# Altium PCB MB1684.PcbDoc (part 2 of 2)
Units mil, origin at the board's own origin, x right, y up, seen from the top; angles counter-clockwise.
Board outline 3937.01 x 905.51 mil, 2 copper layers (Top Layer, Bottom Layer), stack 61.811 mil thick; 71 components, 77 nets, 327 pads, 286 vias.
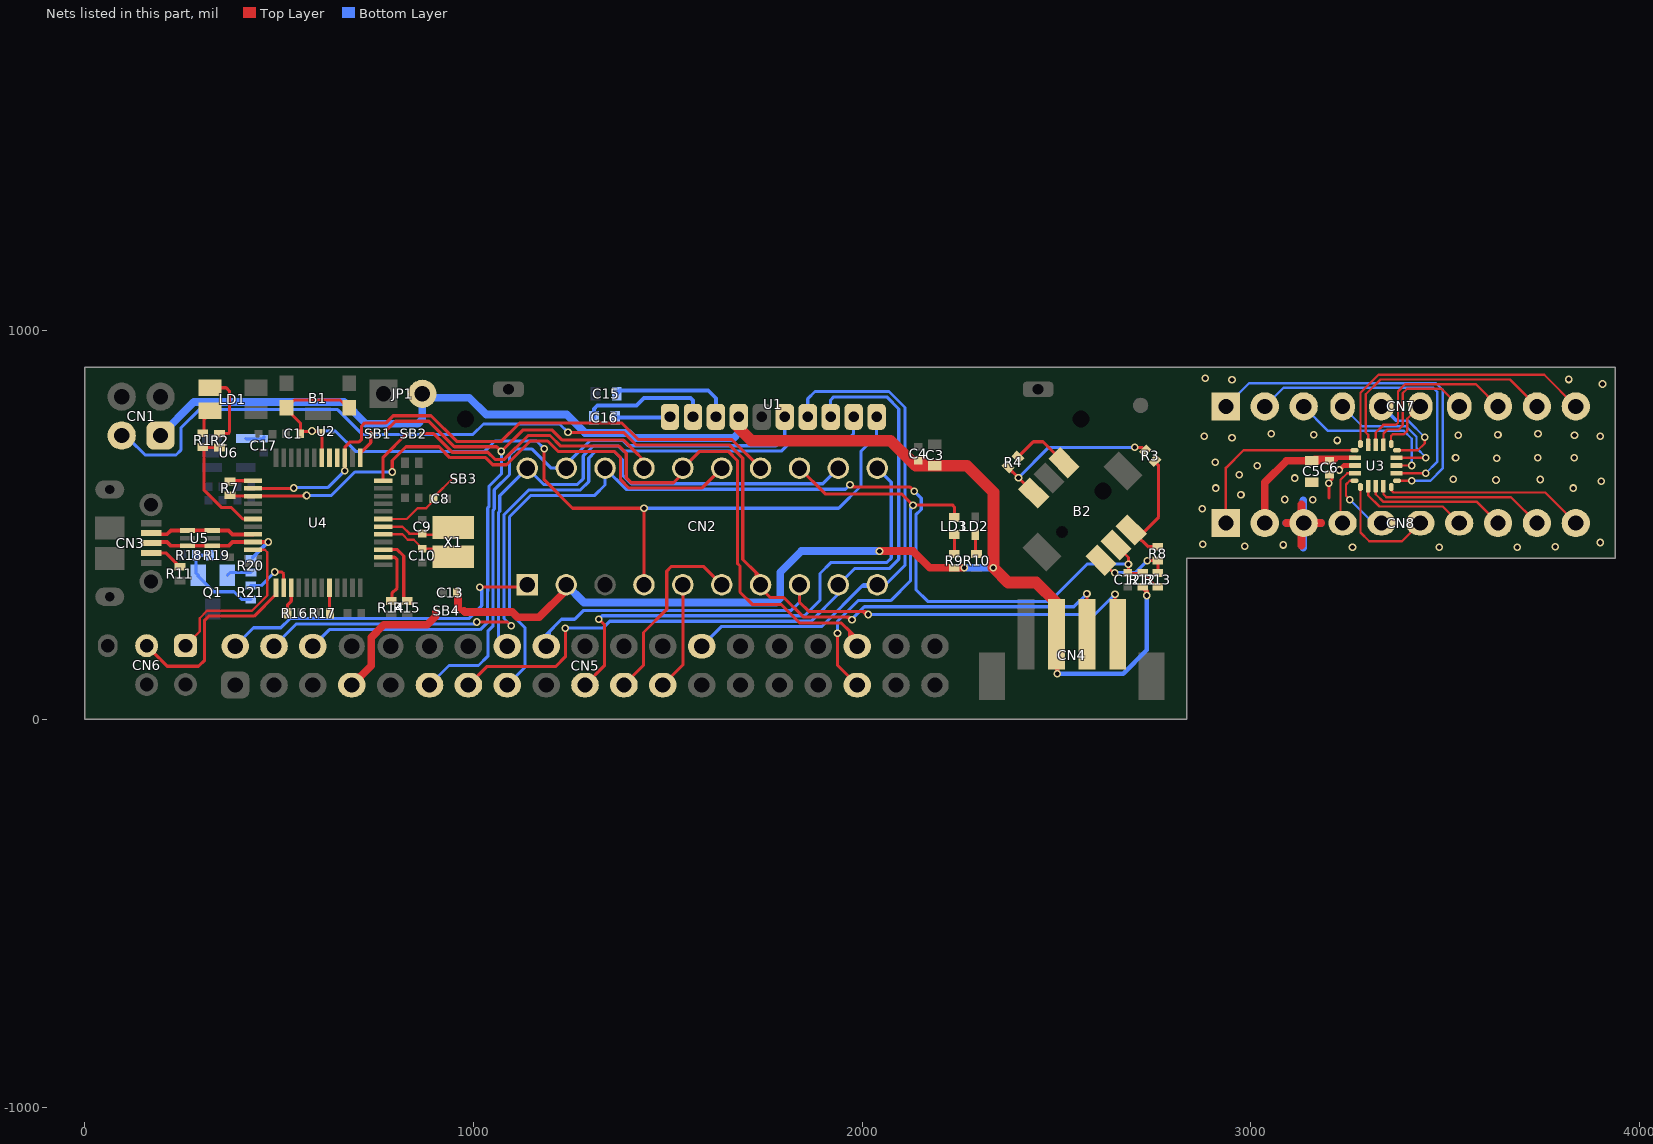
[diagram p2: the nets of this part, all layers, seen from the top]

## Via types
v1: diameter 19.68, hole 11.81, Top Layer to Bottom Layer, tented both sides, 286 vias

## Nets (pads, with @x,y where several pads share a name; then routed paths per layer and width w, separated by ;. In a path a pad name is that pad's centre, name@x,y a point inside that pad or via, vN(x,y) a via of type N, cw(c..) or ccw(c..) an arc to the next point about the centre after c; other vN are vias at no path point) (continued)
NetB2_1: B2.1 R8.1 R13.2 | length 212.5
  Top Layer w8: B2.1@2614.26,408.9 2646.81,376.34 v1(2649.48,376.34) ; v1(2733.85,407.77) 2760.72,407.77 R8.1@2760.83,407.88 R13.2@2760.83,375.77
  Bottom Layer w8: v1@2644.85,376.77 2702.85,376.77 v1(2733.85,407.77) 2736.27,407.77 v1@2736.53,407.52
NetB2_3: B2.3 R3.1 R8.2 | length 306.9
  Top Layer w8: B2.3@2700.54,478.51 B2.3@2705.63,473.42 ; R3.1@2753.37,665.14 2753.37,661.18 2762.85,651.7 2762.85,519.47 2716.79,473.42 B2.3@2705.63,473.42 ; R3.1@2757.98,665.14 R3.1@2757.98,671.28 ; R8.2@2760.83,443.31 2735.74,443.31 B2.3@2705.63,473.42
NetB2_4: B2.4 R3.2 R4.1 | length 456.1
  Top Layer w8: R4.1@2375.03,648.12 v1(2402.4,620.75) B2.4@2441.65,581.5 ; v1(2701.4,698.93) 2706.17,698.93 2719.59,698.93 R3.2@2728.32,690.2
  Bottom Layer w8: v1(2402.4,620.75) 2480.58,698.93 v1(2701.4,698.93)
NetB2_6: B2.6 R4.2 | length 157.7
  Top Layer w8: R4.2@2400.81,673.9 2440.51,713.6 2465.45,713.6 B2.6@2519.6,659.45
NetC15_2: C15.2 U1.8 | length 314.1
  Bottom Layer w10: C15.2@1369.19,836.61 1377.51,844.93 1604.4,844.93 1624.02,825.32 U1.8@1624.02,777.56
NetC16_1: C16.1 U1.10 | length 141.5
  Bottom Layer w10: C16.1@1365.26,775.59 1503.94,775.59 U1.10@1505.91,777.56
NetC16_2: C16.2 U1.9 | length 333.6
  Bottom Layer w10: C16.2@1310.14,775.59 1310.14,798.1 1318.96,806.93 1420.12,806.93 1438.97,825.78 1559.11,825.78 1564.96,819.93 U1.9@1564.96,777.56
NetC17_2: C17.2 U6.4 | length 48.9
  Bottom Layer w8: U6.4@414.64,722 415.66,720.98 C17.2@461.13,720.98 ; C17.2@461.13,726.03 C17.2@463.13,726.03
NetCN3_4: CN3.4 R11.2 | length 88.6
  Top Layer w8.27: CN3.4@171.26,427.17 210.3,427.17 R11.2@245.35,392.11
NetCN5_7: CN5.7 SB4.2 | length 341.2
  Top Layer w20: CN5.7@687.4,87.8 737.4,137.8 737.4,209.89 770.06,242.55 881.18,242.55 903.22,264.58 903.22,274.55
NetLD1_2: LD1.2 R1.2 | length 67.5
  Top Layer w7.87: R1.2@307.09,735.23 307.09,770.46 LD1.2@329.92,793.3
NetLD1_3: LD1.3 R2.2 | length 179.7
  Top Layer w7.87: LD1.3@329.92,852.35 364.28,852.35 373.15,843.49 373.15,738.06 369.34,734.25 R2.2@347.4,734.25
NetLD2_1: LD2.1 R10.1 | length 49.5
  Top Layer w8: R10.1@2291.54,424.99 LD2.1@2291.54,474.45
NetLD3_1: LD3.1 R9.1 | length 55.4
  Top Layer w8: R9.1@2237.4,424.99 LD3.1@2237.4,480.35
NetQ1_1: Q1.1 R18.2 R19.1 R21.1 | length 248.4
  Bottom Layer w8: R19.1@319.17,421.71 R18.2@287.1,421.71 287.1,375.32 Q1.1@292.52,369.9 292.52,367.2 332.13,327.6 384.33,327.6 403.81,308.11 R21.1@427.63,308.11
NetQ1_2: Q1.2 R20.2 | length 63.8
  Bottom Layer w8: Q1.2@367.32,369.9 374.64,377.22 R20.2@428.13,377.22
NetR14_2: R14.2 U4.2 | length 150.1
  Top Layer w8: U4.2@768.03,416.34 797.77,416.34 804.22,409.89 804.22,336.96 790.67,323.42 R14.2@790.67,304.26
NetR15_2: R15.2 U4.3 | length 178.9
  Top Layer w8: U4.3@768.03,436.02 804.7,436.02 821.13,419.6 821.13,313.18 R15.2@830.04,304.26
NetR16_1: R16.1 U4.39 | length 76
  Top Layer w8: R16.1@522.59,272.55 522.59,294.2 531.81,303.42 U4.39@531.81,337.6 U4.39@531.81,344.75
NetR17_2: R17.2 U4.44 | length 72.4
  Top Layer w8: R17.2@629.78,272.55 630.24,273 U4.44@630.24,337.6 U4.44@630.24,344.75
NRST: B1.1 B1.3 C1.2 CN2.7 U1.1 U2.1 U4.18 | length 2353.4
  Top Layer w7.87: C1.2@559.13,738.6 C1.2@557.31,740.41 ; U2.1@605.74,742.6 U2.1@603.55,740.41 ; U2.1@609.82,740.41 U2.1@603.55,740.41 ; U4.18@610.55,679.39 U2.1@610.55,740.41 ; B1.3@681.1,799.47 B1.3@681.1,801.17 677.12,801.17 657.2,821.1 539.61,821.1 B1.1@519.68,801.17 526.13,794.73 526.13,790.6 555.13,761.6 555.13,742.6 C1.2@557.31,740.41 ; v1(1182.13,695.65) 1182.13,615.6 1255.18,542.54 v1(1439.1,542.54) 1439.1,345.78 CN2.7@1438.98,345.65 ; C1.2@557.31,740.41 U2.1@603.55,740.41
  Bottom Layer w7.87: v1(585.13,741.25) 645.27,741.25 697.73,688.78 1029.52,688.78 1055.99,715.25 1162.53,715.25 v1(1182.13,695.65) ; v1(1439.1,542.54) 1939.82,542.54 1997.1,599.82 1997.1,689.39 2037.4,729.69 U1.1@2037.4,777.56
OSC_IN: C10.2 U4.5 X1.1 | length 208.1
  Top Layer w6: U4.5@768.03,475.39 817.69,475.39 831.69,461.39 846.22,461.39 846.38,461.24 846.8,461.24 C10.2@869.58,438.46 ; C10.2@869.5,438.46 C10.2@869.58,438.46 ; C10.2@873.44,438.3 869.74,438.3 C10.2@869.58,438.46 ; X1.1@948.24,417.73 927.51,438.46 C10.2@869.58,438.46
OSC_OUT: C9.2 U4.6 X1.2 | length 199.2
  Top Layer w6: U4.6@768.03,495.08 817.8,495.08 835.61,477.27 C9.2@872.57,477.27 ; C9.2@868.63,474.07 929.78,474.07 X1.2@948.24,492.53
PA0: CN2.9 CN5.23 | length 279.2
  Top Layer w8: CN5.23@1487.4,87.8 1538.98,139.37 CN2.9@1538.98,345.65
PA1: CN2.11 CN5.21 | length 504.7
  Top Layer w8: CN5.21@1387.4,87.8 1437.98,138.37 1437.98,222.99 1497.57,282.58 1497.57,380.85 1509.69,392.97 1591.66,392.97 CN2.11@1638.98,345.65
PA2: CN1.2 CN2.13 CN4.2 | length 3166.9
  Top Layer w8: v1(1243.57,737.6) 1386.53,737.6 1418.63,705.49 1658.68,705.49 1693.13,671.05 1693.13,410.72 1727.65,376.2 ; CN2.13@1727.65,337.33 1727.65,376.2 ; 1727.65,376.39 1727.65,376.2 ; 1960.96,262.85 v1@1968.82,255 ; v1(1974.13,255.25) 1966.27,263.1 1848.32,263.1 1798.34,313.09 1763.92,313.09 1738.98,338.03 CN2.13@1738.98,345.65 1738.98,364.87 1727.65,376.2 ; v1(2578.4,322.93) 2578.4,218.17 CN4.2@2578.74,218.5
  Bottom Layer w8: CN1.2@115.35,729.53 115.35,719.92 155.96,679.31 235.42,679.31 248,691.89 248,749 295,796 651.1,796 714.64,732.46 999.43,732.46 1026.26,759.29 1221.87,759.29 v1(1243.57,737.6) ; v1@1975.13,258.25 2005.98,289.1 2544.58,289.1 v1(2578.4,322.93)
PA3: CN2.15 CN4.1 CN5.18 | length 1814.1
  Top Layer w8: CN2.15@1838.98,345.65 1838.98,301.02 1862.9,277.1 2008.13,277.1 v1(2015.98,269.26) ; 2002.96,276 v1@2010.82,268.15 ; CN4.1@2647.03,208.05 CN4.1@2647.4,207.68 ; v1(2650.59,321.57) 2650.59,225.39 CN4.1@2657.48,218.5
  Bottom Layer w8: CN5.18@1196.43,194.47 CN5.18@1196.43,196.83 ; 1196.43,224.04 CN5.18@1196.43,196.83 ; CN5.18@1198.34,198.73 CN5.18@1196.43,196.83 ; CN2.15@1838.98,345.65 1838.98,301.02 1817.88,279.93 1283.74,279.93 1260.79,256.98 1227.01,256.98 1187.4,217.36 CN5.18@1187.4,187.8 CN5.18@1196.43,196.83 ; v1(2015.98,269.26) 2598.28,269.26 v1(2650.59,321.57)
PA4: CN2.17 CN5.13 U1.3 | length 1919
  Top Layer w8: CN5.13@987.4,87.8 1034.58,134.98 1211.48,134.98 1236.84,160.34 v1(1236.84,233.98)
  Bottom Layer w8: v1(1236.84,233.98) 1332.89,233.98 1350.84,251.93 1868.98,251.93 1938.98,321.92 CN2.17@1938.98,345.65 1980.58,387.26 2070.07,387.26 2094.4,411.59 2094.4,797.93 2063.52,828.81 1927.29,828.81 1919.29,820.81 U1.3@1919.29,777.56
PA5: CN2.19 CN5.26 U1.4 | length 1372.1
  Bottom Layer w8: CN5.26@1587.4,187.8 1637.53,237.93 1895.64,237.93 2003.37,345.65 CN2.19@2038.98,345.65 2060.25,345.65 2110.4,395.81 2110.4,801.73 2069.32,842.81 1879.12,842.81 1860.24,823.93 U1.4@1860.24,777.56 ; 1999.84,340.98 CN2.19@2035.45,340.98
PA6: CN2.2 CN5.16 U1.2 | length 1502.2
  Bottom Layer w8: CN5.16@1087.4,187.8 1078.16,187.8 1065.11,200.85 1065.11,531.77 1067.95,534.61 1067.95,574.62 CN2.2@1138.98,645.65 1181.04,603.59 1267.8,603.59 1282.98,618.76 1282.98,677.26 1307.98,702.26 1373.98,702.26 1386.98,689.26 1792.4,689.26 1823.14,720 1963.77,720 1978.35,734.57 U1.2@1978.35,777.56
PA7: CN2.4 CN5.11 U1.5 | length 1560.3
  Bottom Layer w8: CN5.11@887.4,87.8 937.53,137.93 1013.53,137.93 1037.4,161.8 1037.4,226.45 1051.1,240.15 1051.1,323.61 ; 1051.11,323.62 1051.11,537.56 1053.95,540.41 1053.95,589.77 1093.13,628.95 1093.13,678.8 1108.87,694.55 1151.25,694.55 1200.14,645.65 CN2.4@1238.98,645.65 1244.53,645.65 1244.53,660.65 1300.13,716.26 1385.77,716.26 1398.77,703.26 1779.03,703.26 1801.18,725.41 U1.5@1801.18,777.56
PA8: B2.2 C12.2 CN2.6 CN5.15 R12.2 R13.1 | length 2669.2
  Top Layer w6: C12.2@2685.44,375.77 R12.2@2721.66,375.77 2723.96,375.77 2759.39,340.34 R13.1@2760.83,340.34
  Top Layer w8: v1(1968.86,602.8) 1975.02,596.64 2123.56,596.64 v1(2134.4,585.8) ; v1@1973.32,603.5 1979.48,597.34 ; B2.2@2653.23,447.87 2685.13,415.98 v1(2685.13,398.6) 2685.44,398.28 C12.2@2685.44,375.77
  Bottom Layer w8: CN5.15@1087.4,87.8 1132.83,133.23 1132.83,235.17 1093.11,274.89 1093.11,520.17 1148.52,575.59 1312.46,575.59 1338.98,602.1 CN2.6@1338.98,645.65 1393.33,591.3 1957.36,591.3 v1(1968.86,602.8) ; v1(2134.4,585.8) 2152.1,568.09 2152.1,539.4 2138.4,525.71 2138.4,333.4 2168.71,303.1 2483.2,303.1 2578.69,398.6 v1(2685.13,398.6)
PA9: CN2.8 CN5.6 SB1.1 | length 1733
  Top Layer w8: SB1.1@775.13,734.25 775.13,741.38 800.05,766.31 885.61,766.31 951.36,700.57 1060.15,700.57 v1(1072.13,688.6) 1127.03,743.49 1203.24,743.49 1229.23,717.51 1386.81,717.51 1412.83,691.49 ; 1412.85,691.49 1438.98,665.37 CN2.8@1438.98,645.65
  Bottom Layer w8: CN5.6@587.4,202.93 CN5.6@587.4,187.8 ; CN5.6@588.21,187.8 CN5.6@587.4,187.8 ; v1(1072.13,688.6) 1072.13,630.65 1039.95,598.47 1039.95,546.21 1037.11,543.36 1037.11,329.41 1037,329.31 1037,249.66 1017.5,230.16 629.76,230.16 CN5.6@587.4,187.8
PA10: CN2.10 CN5.34 SB2.1 | length 1766.9
  Top Layer w8: SB2.1@866.69,734.25 897.87,734.25 945.56,686.57 1037.57,686.57 1055.92,668.22 1079.81,668.22 1141.09,729.49 1197.45,729.49 1224.68,702.26 1375.11,702.26 1393.54,683.83 1393.54,620.83 1406.28,608.09 1514.89,608.09 CN2.10@1552.45,645.65 ; CN2.10@1538.98,645.65 1582.08,688.75 1655.62,688.75 1679.13,665.25 1679.13,400.91 1686,394.04 1686,326.75 1717.36,295.39 1791.65,295.39 1839.53,247.51 1946.67,247.51 1967.96,226.22 ; 1967.96,226.22 1987.4,206.78 CN5.34@1987.4,187.8 1967.96,207.24 1967.96,226.22
PA13: CN2.12 R7.2 U4.27 | length 1484.8
  Top Layer w8: R7.2@374.13,575.88 376.19,573.82 U4.27@433.39,573.82 569.74,573.82 v1(571.18,575.25) ; v1(791.57,635.66) 791.57,665.1 827.03,700.57 911.76,700.57 939.76,672.57 1031.77,672.57 1050.12,654.22 1085.61,654.22 1146.89,715.49 1191.35,715.49 1218.59,688.26 1362.93,688.26 1379.13,672.06 1379.13,615.45 1400.48,594.09 1587.42,594.09 CN2.12@1638.98,645.65
  Bottom Layer w8: v1(571.18,575.25) 635.06,575.25 695.47,635.66 v1(791.57,635.66)
PA14: CN2.14 U4.15 U4.26 | length 1533.4
  Top Layer w8: U4.26@433.39,593.5 535.59,593.5 536.74,594.66 v1(538.57,594.66) ; v1(669,638.73) 669.61,639.34 U4.15@669.61,672.24 669.61,699.74 683.13,713.26 706.52,713.26 712.9,719.63 712.9,753.83 721.1,762.03 775.97,762.03 794.25,780.31 891.41,780.31 957.15,714.57 1072.1,714.57 1119.43,761.9 1382.02,761.9 1424.43,719.49 1665.14,719.49 CN2.14@1738.98,645.65
  Bottom Layer w8: v1(538.57,594.66) 540.16,596.25 626.52,596.25 v1(669,638.73)
PB6: CN2.16 CN5.33 LD3.2 | length 1075.8
  Top Layer w8: CN2.16@1838.98,645.65 1905.14,579.49 2101.4,579.49 v1(2131.09,549.8) 2132.47,551.17 2231.94,551.17 2237.4,545.71 LD3.2@2237.4,523.66 ; v1@1937.13,211.98 1937.13,138.07 CN5.33@1987.4,87.8
  Bottom Layer w8: v1(1936.84,221.11) 1937.13,221.4 1937.13,252.62 1989.48,304.98 2073.39,304.98 2124.4,355.99 2124.4,543.11 v1(2131.09,549.8) ; 2125.4,539.55 v1@2132.09,546.24
PB7: CN2.18 CN5.4 | length 1959.6
  Top Layer w8: 1020,250 1088,250 v1(1098,240)
  Bottom Layer w8: CN5.4@487.4,187.8 544.25,244.64 1003.92,244.64 v1(1009.28,250) ; v1(1098,240) 1079.11,258.89 1079.11,525.97 1142.72,589.59 1275.55,589.59 1296.98,611.01 1296.98,671.26 1313.98,688.26 1362.93,688.26 1383.45,667.73 1383.45,628.79 1406.66,605.57 1898.9,605.57 CN2.18@1938.98,645.65
PC14: CN2.20 CN5.19 | length 1300.1
  Top Layer w8: CN5.19@1287.4,87.8 1337.84,138.24 1337.84,241.98 v1(1322.84,256.98)
  Bottom Layer w8: v1(1322.84,256.98) 1331.79,265.93 1851.82,265.93 1891.72,305.83 1891.72,374.47 1920.51,403.26 2064,403.26 2074.98,414.24 2074.98,609.65 CN2.20@2038.98,645.65
PC15: CN2.1 CN5.2 | length 862.9
  Top Layer w8: v1@1012,340 1133.32,340 CN2.1@1138.98,345.65
  Bottom Layer w8: CN5.2@387.4,187.8 434.77,235.17 505.17,235.17 528.64,258.64 988.64,258.64 1021.84,291.84 1021.84,334.16 v1(1017,339) ; v1@1016.16,333.84 1021,329
STLK_LED: R1.1 R2.1 U4.30 | length 308.1
  Top Layer w7.87: R2.1@347.4,698.82 308.06,698.82 307.09,699.8 307.09,589.82 352.98,543.93 378.08,543.93 407.25,514.76 U4.30@433.39,514.76
STLK_RST: C8.2 SB3.2 U4.7 | length 224.5
  Top Layer w6: U4.7@768.03,514.76 828.81,514.76 856.7,542.66 878.62,542.66 897.78,561.82 C8.2@897.78,566.55 ; C8.2@901.88,574.19 945.87,618.19 SB3.2@954.16,618.19
STLK_RX: SB1.2 U4.13 | length 76.6
  Top Layer w8: U4.13@708.98,672.24 708.98,684.19 736.13,711.34 SB1.2@736.13,737.6
STLK_SWCLK: CN6.3 U4.37 | length 515.2
  Top Layer w8: CN6.3@159.84,188.98 212.89,135.93 293.4,135.93 309.11,151.64 309.11,254.4 319.64,264.93 436.42,264.93 492.44,320.95 U4.37@492.44,337.6 U4.37@492.44,344.75
STLK_SWDIO: CN6.1 U4.34 | length 434.6
  Top Layer w5.91: CN6.1@259.84,188.98 296.16,225.3 296.16,259.76 315.19,278.8 430.66,278.8 470,318.14 470,429.55 463.53,436.02 U4.34@433.39,436.02
STLK_TX: SB2.2 U4.12 | length 146
  Top Layer w7.87: U4.12@768.03,613.19 768.03,673.98 SB2.2@828.31,734.25
STLK_USB_D_N: CN3.2 U4.32 U5.1 U5.6 | length 267.4
  Top Layer w10: CN3.2@174.05,475.55 212.51,475.55 222.19,485.24 U5.1@265.31,485.24 U5.6@328.69,485.24 370.82,485.24 380.67,475.39 U4.32@433.39,475.39
STLK_USB_D_P: CN3.3 R20.1 U4.33 U5.3 U5.4 | length 366.1
  Top Layer w10: CN3.3@171.26,452.76 174.05,455.55 212.51,455.55 222.19,445.87 U5.3@265.31,445.87 U5.4@328.69,445.87 370.83,445.87 380.67,455.71 U4.33@433.39,455.71 v1(472.22,455.71)
  Bottom Layer w10: R20.1@432.68,416.17 v1(472.22,455.71)
T_JTDI: U4.17
T_JTDO: U4.16
T_SWDIO_IN: R7.1 U4.25 | length 60
  Top Layer w8: R7.1@374.13,611.31 376,613.19 U4.25@433.39,613.19
TGND: C5.1 C6.1 CN8.3 U3.3 | length 501
  Top Layer w7.87: 3200.5,569.05 v1(3200.5,607.08) 3200.5,608.82 3208.66,616.98
  Top Layer w11.81: v1(3227.25,640.74) 3238.92,652.42 U3.3@3268.13,652.42
  Top Layer w20: 3091.89,504.38 CN8.3@3129.92,504.38 ; 3129.92,446.42 CN8.3@3129.92,504.38 ; 3129.92,552.25 CN8.3@3129.92,504.38 ; 3181.05,504.38 CN8.3@3135.83,504.38 CN8.3@3129.92,504.38
  Bottom Layer w20: 3091.94,504.38 CN8.3@3134.94,504.38 ; 3134.94,441.42 CN8.3@3134.94,504.38 ; 3134.94,562.42 CN8.3@3134.94,504.38 ; 3179.94,504.38 CN8.3@3135.83,504.38 CN8.3@3134.94,504.38
  other v1: 3261.5,442.08 3484.92,442.08 3685.36,442.08 3782.5,443.08 2984.5,444.83 3083.32,448.12 2875.96,449.49 3898.5,454.38 2874.65,541.39 3159.09,564.38 3087.58,565.01 2974.5,577.52 2910.08,594.35 3829.5,594.35 3901.5,612.08 3630.5,615.08 3744.5,616.32 3520.5,617.49 3112.5,620.08 2970.5,628.49 3016.5,651.8 2908.5,661.14 3632.5,671.08 3526.5,672.58 3737.5,672.08 3831.5,672.25 3222.4,716.91 2951.5,724.08 2879.81,727.22 3898.5,727.22 3533.5,730.44 3832.5,730.44 3161.4,731.3 3635.5,731.08 3738.5,733.65 3052.5,734.08 3904.5,862.08 2951.5,872.55 3817.5,873.8 2882.96,876.49
TNRST: CN8.4 U3.4 | length 158
  Top Layer w6: CN8.4@3235.83,504.38 3230.52,509.69 3230.52,602.23 3230.68,602.39 3230.68,615.63 3247.79,632.73 U3.4@3268.13,632.73
TPA0: CN8.5 U3.5 | length 222.3
  Top Layer w6: v1(3254.5,564.76) 3244.68,574.58 3244.68,603.23 3254.5,613.05 U3.5@3266.16,613.05 ; CN8.5@3302.93,504.38 CN8.5@3335.83,504.38 3335.83,509.67 CN8.5@3328.95,516.55
  Bottom Layer w6: v1(3254.5,564.76) 3314.88,504.38 CN8.5@3335.83,504.38
TPA1: CN8.6 U3.6 | length 299.9
  Top Layer w6: U3.6@3281.91,597.3 3281.91,480.12 3304.53,457.49 3388.94,457.49 CN8.6@3435.83,504.38
TPA2: CN8.7 U3.7 | length 287.2
  Top Layer w6: U3.7@3301.6,599.27 3301.6,575.91 3330.62,546.88 3493.33,546.88 CN8.7@3535.83,504.38
TPA3: CN8.8 U3.8 | length 366
  Top Layer w6: U3.8@3321.28,599.27 3321.28,578.55 3340.95,558.88 3581.33,558.88 CN8.8@3635.83,504.38
TPA4: CN8.9 U3.9 | length 446.3
  Top Layer w6: U3.9@3340.97,599.27 3340.97,578.55 3348.63,570.88 3669.33,570.88 CN8.9@3735.83,504.38
TPA5: CN8.10 U3.10 | length 518.4
  Top Layer w6: U3.10@3360.65,597.3 3360.65,589.16 3366.93,582.88 3757.33,582.88 CN8.10@3835.83,504.38
TPA6: CN7.1 U3.11 | length 921.7
  Top Layer w6: U3.11@3376.4,613.05 v1(3414.26,613.05)
  Bottom Layer w6: CN7.1@2935.83,804.38 2995.83,864.38 3475.83,864.38 3493.18,847.03 3493.18,644.5 3461.72,613.05 v1(3414.26,613.05)
TPA7: CN7.2 U3.12 | length 764.4
  Top Layer w6: U3.12@3374.43,632.73 v1(3450.09,632.73)
  Bottom Layer w6: CN7.2@3035.83,804.38 3083.83,852.38 3468.77,852.38 3479.09,842.07 3479.09,661.73 v1(3450.09,632.73)
TPA8: CN7.3 U3.13 | length 421.2
  Top Layer w6: U3.13@3374.43,652.42 v1(3414.09,652.42)
  Bottom Layer w6: CN7.3@3135.83,804.38 3198.74,741.47 3393.91,741.47 3414.09,721.29 v1(3414.09,652.42)
TPA9: CN7.4 U3.14 | length 351.7
  Top Layer w6: U3.14@3384.56,674.03 3386.49,672.1 v1(3449.52,672.1) v1@3450.09,672.1
  Bottom Layer w6: CN7.4@3235.83,804.38 3286.74,753.47 3398.88,753.47 3426.09,726.26 3426.09,697.42 v1@3450.09,673.42
TPA10: CN7.5 U3.15 | length 290.6
  Top Layer w6: U3.15@3376.4,691.79 3429.46,691.79 3447.06,709.39 v1(3447.06,725.33)
  Bottom Layer w6: CN7.5@3335.83,804.38 3373.08,767.13 3405.26,767.13 v1(3447.06,725.33) ; CN7.5@3339.74,804.68 3376.99,767.42
TPA13: CN7.6 U3.16 | length 145.9
  Top Layer w6: U3.16@3360.65,707.53 3360.65,728.51 3365.11,732.97 3393.91,732.97 3402.41,741.47 3402.41,772.68 3434.11,804.38 CN7.6@3435.83,804.38
TPA14: CN7.7 U3.17 | length 339.1
  Top Layer w6: U3.17@3340.97,705.57 3340.97,734.75 3351.18,744.97 3380.2,744.97 3390.41,755.18 3390.41,838.09 3402.12,849.8 3490.41,849.8 CN7.7@3535.83,804.38
TPB6: CN7.8 U3.18 | length 468.8
  Top Layer w6: U3.18@3321.28,705.57 3321.28,737.3 3340.95,756.97 3372.8,756.97 3378.41,762.57 3378.41,843.06 3397.15,861.8 3578.41,861.8 CN7.8@3635.83,804.38
TPB7: CN7.9 U3.19 | length 620.6
  Top Layer w6: U3.19@3304.37,705.57 U3.19@3301.6,705.57 3301.6,731.72 3295.33,737.99 3295.33,835.87 3333.26,873.8 3666.41,873.8 CN7.9@3735.83,804.38
TPC14: CN7.10 U3.20 | length 738.7
  Top Layer w6: U3.20@3281.91,707.53 3281.91,839.42 3328.29,885.8 3754.41,885.8 CN7.10@3835.83,804.38
TPC15: CN8.1 U3.1 | length 491.1
  Top Layer w6: CN8.1@2935.83,504.38 2935.83,646.23 2981.38,691.79 U3.1@3266.16,691.79
TVDD: C5.2 C6.2 CN8.2 U3.2 | length 422.2
  Top Layer w11.81: C5.2@3156.34,664.7 3163.73,672.1 U3.2@3268.13,672.1 ; C5.2@3162.75,661.14 3212.25,661.14 3219.25,668.14
  Top Layer w20: CN8.2@3035.83,504.38 3035.83,608.64 3091.89,664.7 C5.2@3156.34,664.7
USB_RENUMn: R21.2 U4.38 | length 137.1
  Top Layer w8: v1(489.22,378.55) 507.22,378.55 512.13,373.64 U4.38@512.13,337.6
  Bottom Layer w8: R21.2@427.63,343.55 454.22,343.55 v1(489.22,378.55)
VDD: C3.2 C4.2 C13.2 CN1.1 CN2.3 CN4.3 JP1.2 R9.2 R12.1 SB4.1 U1.7 | length 5099.1
  Top Layer w12: CN4.3@2500,244.09 2500.5,244.6 2506.89,238.21 2502.4,233.72 v1(2502.4,116.93) ; R12.1@2724.22,340.34 2726.84,337.72 2725.1,335.98 2732.4,328.67 v1(2732.4,317.93)
  Top Layer w20: 960.4,281.54 C13.2@960.4,322.25 ; 976.02,278.3 978.48,275.84 1100,275.84 1113.84,262 1169,262 1238.98,331.98 CN2.3@1238.98,345.65 ; v1(2044.8,432.25) 2131.09,432.25 2173.79,389.55 R9.2@2237.4,389.55 2237.56,389.39 v1(2263,389.39)
  Top Layer w30: U1.7@1683.07,777.56 1683.07,748.82 1715.63,716.26 2073.18,716.26 2128.73,660.71 ; 2152.1,651.71 2137.73,651.71 2128.73,660.71 ; 2153.23,651.57 C3.2@2187.4,651.57 2269.91,651.57 2337.98,583.51 2337.98,389.55 2376.22,351.31 2447.93,351.31 2500,299.24 2500,244.09 CN4.3@2500,218.5 ; C4.2@2154.1,660.71 2128.73,660.71
  Bottom Layer w12: v1(2502.4,116.93) 2671.46,116.93 2732.4,177.87 v1(2732.4,317.93)
  Bottom Layer w20: CN1.1@195.67,729.53 195.67,730.08 281.59,816 667.54,816 723.6,759.94 857.84,759.94 868.98,771.08 JP1.2@868.98,836.61 878.8,826.8 989.78,826.8 1033.11,783.46 1240.15,783.46 1287.35,736.26 1399.98,736.26 1412.98,723.26 1670.06,723.26 1683.07,736.27 U1.7@1683.07,777.56 ; CN2.3@1238.98,345.65 1284.7,299.93 1778.34,299.93 1789.37,310.96 1789.37,378.05 1843.57,432.25 v1(2044.8,432.25) ; v1(2263,389.39) v1(2337.82,389.39)
pads on no net: B2.NPTH1 B2.NPTH2 CN1.3 CN4.0 CN5.1 CN5.3 CN5.5 CN5.10 CN5.12 CN5.14 CN5.17 CN5.22 CN5.24 CN5.25 CN5.27 CN5.28 CN5.29 CN5.30 CN5.31 CN5.35 CN5.36 CN5.37 CN5.38 CN6.5 M1. U1.0 U1.A U1.K U4.4 U4.11 U4.14 U4.19 U4.21 U4.22 U4.28 U4.29 U4.31 U4.40 U4.41 U4.42 U4.43 U4.45 U4.46

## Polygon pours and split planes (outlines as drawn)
GND on Top Layer "Bottom Layer-No Net 1" (solid, remove dead copper, pour order 18): 0,905.51 2834.65,905.51 2834.65,0 0,0
TGND on Top Layer "Bottom Layer-No Net 1" (solid, remove dead copper, pour order 14): 2834.65,905.51 3937.01,905.51 3937.01,413.39 2834.65,413.39
GND on Bottom Layer "Bottom Layer-No Net 1" (solid, remove dead copper, pour order 20): 0,905.51 2834.65,905.51 2834.65,0 0,0
TGND on Bottom Layer "Bottom Layer-No Net 1" (solid, remove dead copper, pour order 16): 2834.65,905.51 3937.01,905.51 3937.01,413.39 2834.65,413.39

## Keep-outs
Keep-Out Layer:
  circle w7.87: c2834.65,866.15 r19.68
  circle w7.87: c2834.65,807.09 r19.68
  circle w7.87: c2834.65,748.04 r19.68
  circle w7.87: c2834.65,688.98 r19.68
  circle w7.87: c2834.65,629.93 r19.68
  circle w7.87: c2834.65,570.87 r19.68
  circle w7.87: c2834.65,511.82 r19.68
  circle w7.87: c2834.65,452.76 r19.68
  lines w7.87: 0,0 2834.65,0 2834.65,413.39 3937.01,413.39 3937.01,905.51 2834.65,905.51 0,905.51 0,0

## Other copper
Top Layer:
  pour cut-out: 2311.38,498.23 2306.84,502.77 2214.4,502.77 2214.4,416.02 2221.4,409.02 2224.37,411.99 2288.4,411.99 2288.4,458.99 2296.4,466.99
  region net GND: 2435.13,325.82 2457.91,305.11 2468.22,248.31 2436.71,216.8 2377.69,216.8 2369.4,225.09 2369.4,320.66 2388,320.66 2389.61,319.06
  region net GND: 2427.4,254.8 2433.17,249.03 2464.4,249.03 2464.4,149.8 2449.58,134.98 2417.4,134.98
  region net GND: 16.06,615.81 16.06,281.44 36.21,261.29 52.21,277.29 65.21,277.29 65.21,306.29 58.21,313.29 64.96,320.05 64.96,647.01
  pour cut-out: 3281.91,707.53 3360.65,707.53 3376.4,691.79 3376.4,613.05 3360.65,597.3 3281.91,597.3 3266.16,613.05 3266.16,691.79
  text ".Layer_Name" at 189.34,-695.37 h118.11
  text ".GTL" at 1830.87,-695.37 h118.11
Bottom Layer:
  text ".GBL" at 1389.79,-696.63 h118.11
  text ".Layer_Name" at 3016.33,-696.63 h118.11

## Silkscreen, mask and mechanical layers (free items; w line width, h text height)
Top Overlay:
  lines w3.94: 288,246.82 506.4,246.82 ; 392.3,715.49 462.16,715.49 ; 636.45,724.64 651.84,709.25 ; 943,542.28 1056.93,542.28
  lines w5: 2111.1,543.55 2230.1,543.55
  text "MB1684B" at 2074.78,777.56 h80
  text "J" at 1169.27,729.49 h400
  text "LCD: NHD-C0216CZ-FSW-FBW-3V3" at 1418.63,705.49 h55.12
  text "MB1684B_D" at 3526.5,640.13 h80
  text "MORPHO" at 282.1,628.12 h55.12 r90
  text "UP" at 2367.4,508.55 h55.12 r90
  text "MORPHO" at 1594.28,240.88 h55.12
  text "USB" at 127.2,240.48 h55.12
  text "SWD" at 17.56,81.89 h55.12
  text ".Layer_Name" at 189.34,-695.37 h118.11
  text ".GTO" at 1830.87,-695.37 h118.11
Bottom Overlay:
  lines w5: 289.33,877 450.23,877 450.23,743.81 ; 292.52,877 287.1,877 287.1,528.55 449,528.55 449,614.53
  text "F" at 2356,682 h400
  text "G" at 2400.81,446.67 h400
  text "C" at 1679.13,436.02 h300
  text "H" at 1446.84,417.73 h400
  text "S" at 1938.73,403.26 h300
  text "E" at 2502.51,84.8 h400
  text "I" at 2741.81,81.8 h400
  text ".GBO" at 1389.79,-696.63 h118.11
  text ".Layer_Name" at 3016.33,-696.63 h118.11
Top Paste:
  text ".Layer_Name" at 189.34,-695.37 h118.11
  text ".GTP" at 1830.87,-695.37 h118.11
Bottom Paste:
  text ".GBP" at 1389.79,-696.63 h118.11
  text ".Layer_Name" at 3016.33,-696.63 h118.11
Top Solder:
  text ".Layer_Name" at 189.34,-695.37 h118.11
  text ".GTS" at 1830.87,-695.37 h118.11
Bottom Solder:
  text ".GBS" at 1389.79,-696.63 h118.11
  text ".Layer_Name" at 3016.33,-696.63 h118.11
M1-Board Shape:
  lines w7.87: 0,0 0,905.51 3937.01,905.51 3937.01,413.39 2834.65,413.39 2834.65,0 0,0
M2-Board Dimensions:
  text ".Layer_Name" at 189.34,-695.37 h118.11
  text ".GM2" at 1830.87,-695.37 h118.11
M14-Top Assembly:
  text ".Layer_Name" at 189.34,-695.37 h118.11
  text ".GM14" at 1830.87,-695.37 h118.11
M15-Bottom Assembly:
  text ".GM15" at 1389.79,-696.63 h118.11
  text ".Layer_Name" at 3016.33,-696.63 h118.11
Drill Drawing:
  drawing of 423 lines, arcs and shapes, not listed
  text "IMPEDANCE TABLE   USB HS STLINK" at 5285.96,3227.1 h118.11
  text "PCB SPECIFICATIONS :" at -2423.54,3168.86 h118.11
  text "PCB : TYPE 3" at 3383.22,3162.07 h118.11
  text "LAYER" at 5453.29,3030.25 h118.11
  text "TRACE" at 6093.05,3030.25 h118.11
  text "SPACING" at 6506.44,3030.25 h118.11
  text "IMPEDANCE" at 7037.93,3030.25 h118.11
  text "IMPEDANCE" at 7707.22,3030.25 h118.11
  text "TOL." at 8445.41,3030.25 h118.11
  text "A.   MATERIAL :" at -2423.54,3011.38 h118.11
  text "FR-4" at -907.79,3011.38 h118.11
  text "TG-170" at -258.18,3011.38 h118.11
  text "X  TG-150" at 460.32,3011.38 h118.11
  text "TG-140" at 1090.24,3011.38 h118.11
  text "ASPECT-RATIO, AXE Z :" at 3383.22,2945.54 h118.11
  text "(mil)" at 6637.34,2932.81 h98.43
  text "(mil)" at 6171.79,2930.84 h98.43
  text "(Single ended)" at 7057.62,2921.98 h98.43
  text "(Differential)" at 7756.44,2921.98 h98.43
  text "B.   MATERIAL FAMILY :" at -2423.54,2893.27 h118.11
  text "N/A" at -907.79,2893.27 h118.11
  text "10" at 6208.1,2779.55 h118.11
  text "+/- 15%" at 8408.21,2778.67 h118.11
  text "WHITE" at -123.2,2777.19 h118.11
  text "C.   SOLDERMASK COLOR :" at -2423.54,2775.16 h118.11
  text "GREEN" at -907.79,2775.16 h118.11
  text "X  BLUE" at 460.32,2775.16 h118.11
  text "BLACK" at 1090.24,2775.16 h118.11
  text "10" at 6658.1,2774.55 h118.11
  text "TOP" at 5304.86,2773.75 h118.11
  text "n/a" at 7170.02,2771.78 h118.11
  text "90 ohm" at 7803.33,2764.86 h118.11
  text "5.3:1 to 8:1 / LEVEL \"B\"" at 3383.96,2679.89 h118.11
  text "D.   SILKSCREEN COLOR :" at -2423.54,2657.05 h118.11
  text "X  WHITE" at -907.79,2657.05 h118.11
  text "YELLOW" at -258.18,2657.05 h118.11
  text "BLACK" at 460.32,2657.05 h118.11
  text "Blue ink PANTONE 2955" at 1090.24,2657.05 h118.11
  text "E.   SURFACE FINISH :" at -2423.54,2538.94 h118.11
  text "X  ENIG" at -907.79,2538.94 h118.11
  text "IMMERSION SILVER" at -258.18,2538.94 h118.11
  text "IMMERSION TIN" at 1090.24,2538.94 h118.11
  text "H.   STACK-UP :" at 5318,2502 h118.11
  text "MINIMUM PARAMETERS" at 3385.02,2459.37 h118.11
  text "HASL" at -907.79,2420.83 h118.11
  text "HASL (PB-FREE)" at -258.18,2420.83 h118.11
  text "GOLDEN FINGER" at 1090.24,2420.83 h118.11
  text "Layer" at 5395.6,2391.97 h60
  text "Name" at 5805.52,2391.97 h60
  text "Material" at 6735.26,2391.97 h60
  text "Thickness" at 7595.03,2391.97 h60
  text "Constant" at 8244.86,2391.97 h60
  text "Board Layer Stack" at 8814.72,2391.97 h60
  text "F.   IMPEDANCE CONTROL :" at -2423.54,2302.72 h118.11
  text "NO" at -907.79,2302.72 h118.11
  text "X  YES  (SEE IMPEDANCE TABLE FOR DETAIL INFORMATION)" at -258.18,2302.72 h118.11
  text "Top Overlay" at 5805.52,2271.97 h60
  text "DEFAULT" at 3385.02,2242.84 h118.11
  text "G.   THROUGH VIA :" at -2423.54,2184.6 h118.11
  text "PLUG THE VIAS WHICH ARE COVERED WITH SOLDERMASK ONE OR TWO SIDE." at -907.79,2184.6 h118.11
  text "Top Solder" at 5805.52,2151.97 h60
  text "Solder Resist" at 6735.26,2151.97 h60
  text "0.59mil" at 7595.03,2151.97 h60
  text "3.4" at 8244.86,2151.97 h60
  text "PLUG MATERIAL :" at -907.79,2066.49 h118.11
  text "X  SOLDERMASK" at 96.15,2066.49 h118.11
  text "NON-CONDUCTIVE EPOXY." at 1090.24,2066.49 h118.11
  text "1" at 5395.6,2031.97 h60
  text "Top Layer" at 5805.52,2031.97 h60
  text "Copper" at 6735.26,2031.97 h60
  text "1.38mil" at 7595.03,2031.97 h60
  text "TRACKS : 6mil        / GAPS : 6mil" at 3385.02,2016.46 h118.11
  text "H.   STACK-UP :" at -2423.54,1948.38 h118.11
  text "SEE LAYER STACK-UP SEQUENCE FOR OVERALL THICKNESS." at -907.79,1948.38 h118.11
  text "Dielectric 1" at 5805.52,1911.97 h60
  text "FR-4" at 6735.26,1911.97 h60
  text "59.06mil" at 7595.03,1911.97 h60
  text "4.6" at 8244.86,1911.97 h60
  text "2" at 5395.6,1791.97 h60
  text "Bottom Layer" at 5805.52,1791.97 h60
  text "Copper" at 6735.26,1791.97 h60
  text "1.38mil" at 7595.03,1791.97 h60
  text "Bottom Solder" at 5805.52,1671.97 h60
  text "Solder Resist" at 6735.26,1671.97 h60
  text "0.59mil" at 7595.03,1671.97 h60
  text "3.4" at 8244.86,1671.97 h60
  text "Bottom Overlay" at 5805.52,1551.97 h60
  text ".Layer_Name" at 189.34,-695.37 h118.11
  text ".DRL" at 1830.87,-695.37 h118.11
M20-Top Title Box:
  circle w10: c3260.37,-959.96 r51.18
  region: 3241.68,-675.07 2630.37,-675.07 2603.04,-744.96 2555.37,-793.19 2500.37,-719.96 2500.37,-654.96 2545.37,-599.96 2601.9,-585.07 3241.68,-585.07
  region: 2690.37,-1003 2266.9,-1003 2306.01,-904.86 2615.37,-904.86 2633.04,-874.96 2719.99,-975.29
  lines w10: 2306.01,-904.86 2652.15,-904.86 2531.43,-765.57 cw(c2602.45,-689.04) 2611.9,-585.07 3271.9,-585.07 3241.9,-675.07 ; 2436.47,-575.34 cw(c2531.99,-613.54) 2541.3,-511.09 ; 2438.01,-574.06 2266.9,-1003 3027.64,-1003 ccw(c3037.42,-895.35) 3137.79,-935.49 ; 2506.51,-728.97 2719.99,-975.29 ; 2516.51,-728.97 2725.37,-969.96 ; 2516.51,-718.97 2725.37,-959.96 ; 2520.37,-675.07 3031.9,-675.07 ; 2521.51,-713.97 2730.37,-954.96 ; 2526.51,-708.97 2735.37,-949.96 ; 2531.51,-703.97 2740.37,-944.96 ; 2536.51,-698.97 2745.37,-939.96 ; 2538.67,-622.1 2747.52,-863.09 ; 2541.35,-511.09 3307.09,-511.09 3137.83,-935.4 ; 2541.51,-693.97 2748.22,-932.49 ; 2541.51,-683.97 2750.37,-924.96 ; 2541.51,-673.97 2750.37,-914.96 ; 2541.51,-638.97 2750.37,-879.96 ; 2546.51,-668.97 2755.37,-909.96 ; 2546.51,-653.97 2755.37,-894.96 ; 2600.52,-905.39 ccw(c2604.65,-884.31) 2616.37,-866.32 ; 2643.29,-674.54 ccw(c2642.27,-696.88) 2629.27,-715.07 2722.37,-822.5 cw(c2651.35,-899.03) 2680.2,-999.37 ; 2890.58,-994.96 3004.34,-665.07 ; 2899.34,-993 3012.3,-665.41 ; 2904.34,-993 3017.3,-665.41 ; 2914.34,-993 3027.3,-665.41 ; 2924.34,-993 3037.3,-665.41 ; 2934.34,-993 3047.3,-665.41 ; 2944.34,-993 3057.3,-665.41 ; 2954.34,-993 3067.3,-665.41 ; 2964.34,-993 3077.3,-665.41 ; 2974.34,-993 3087.3,-665.41 ; 2982.55,-994.96 3096.31,-665.07 ; 3096.31,-675.07 3241.68,-675.07 ; 3215.37,-674.96 3245.37,-584.96 ; 3221.9,-675.07 3251.9,-585.07 ; 3231.9,-675.07 3261.9,-585.07
  lines w11.81: -165,-1156 3378.31,-1156 3378.31,-368.6 -165,-368.6 ; -165,-959.15 2197.2,-959.15 ; -165,-762.3 2197.2,-762.3 ; -165,-565.45 2197.2,-565.45 ; -164.98,-1156 -164.98,-368.6 ; 1409.8,-1156 1409.8,-565.45 ; 2197.2,-1156 2197.2,-368.6 ; 2890.58,-994.96 2982.55,-994.96
  text "Project: '.Board_Name'" at -125.62,-495.21 h118.11
  text "Layer:" at -125.61,-695.37 h118.11
  text "Gerber:" at 1448.74,-695.37 h118.11
  text "Variant: '.VariantName'" at -125.62,-892.22 h118.11
  text "Ref: '.Board_Reference'" at 1453.74,-892.22 h118.11
  text "R" at 3240.37,-989.96 h60
  text "Date: '.Board_Document_Date'" at -125.62,-1089.07 h118.11
  text "Rev: '.Board_PCB_Revision'" at 1451.5,-1089.07 h118.11
M21-Bottom Title Box:
  circle w10: c-39.69,-959.96 r51.18
  region: 530.31,-1003 953.78,-1003 914.67,-904.86 605.31,-904.86 587.64,-874.96 500.69,-975.29
  region: -21,-675.07 590.31,-675.07 617.64,-744.96 665.31,-793.19 720.31,-719.96 720.31,-654.96 675.31,-599.96 618.78,-585.07 -21,-585.07
  lines w10: -41.23,-585.07 -11.23,-675.07 ; -31.23,-585.07 -1.23,-675.07 ; -24.69,-584.96 5.31,-674.96 ; -21.23,-675.07 -51.23,-585.07 608.78,-585.07 cw(c618.23,-689.04) 689.24,-765.57 568.53,-904.86 914.67,-904.86 ; -21,-675.07 124.37,-675.07 ; 82.85,-935.4 -86.41,-511.1 679.32,-511.1 ; 82.89,-935.49 ccw(c183.25,-895.35) 193.04,-1003 953.78,-1003 782.66,-574.06 ; 124.37,-665.07 238.13,-994.96 ; 133.38,-665.41 246.34,-993 ; 143.38,-665.41 256.34,-993 ; 153.38,-665.41 266.34,-993 ; 163.38,-665.41 276.34,-993 ; 173.38,-665.41 286.34,-993 ; 183.38,-665.41 296.34,-993 ; 188.77,-675.07 700.31,-675.07 ; 193.38,-665.41 306.34,-993 ; 203.38,-665.41 316.34,-993 ; 208.38,-665.41 321.34,-993 ; 216.34,-665.07 330.09,-994.96 ; 465.31,-909.96 674.17,-668.97 ; 465.31,-894.96 674.17,-653.97 ; 470.31,-924.96 679.17,-683.97 ; 470.31,-914.96 679.17,-673.97 ; 470.31,-879.96 679.17,-638.97 ; 472.45,-932.49 679.17,-693.97 ; 473.15,-863.09 682.01,-622.1 ; 475.31,-939.96 684.17,-698.97 ; 480.31,-944.96 689.17,-703.97 ; 485.31,-949.96 694.17,-708.97 ; 490.31,-954.96 699.17,-713.97 ; 495.31,-969.96 704.17,-728.97 ; 495.31,-959.96 704.17,-718.97 ; 500.69,-975.29 714.17,-728.97 ; 540.48,-999.37 cw(c569.32,-899.03) 498.31,-822.5 591.41,-715.07 ccw(c578.41,-696.88) 577.39,-674.54 ; 604.31,-866.32 ccw(c616.03,-884.31) 620.16,-905.39 ; 679.37,-511.09 cw(c688.69,-613.54) 784.2,-575.34
  lines w11.81: 238.13,-994.96 330.09,-994.96 ; 1016.1,-1156 1016.1,-368.6 ; 1016.1,-959.15 3378.31,-959.15 ; 1016.1,-762.3 3378.31,-762.3 ; 1016.1,-565.45 3378.31,-565.45 ; 1803.5,-1156 1803.5,-565.45 ; -165,-1156 3378.31,-1156 3378.31,-368.6 -165,-368.6 -165,-1156
  text "Project: '.Board_Name'" at 3331.3,-495.21 h118.11
  text "Gerber:" at 1756.94,-695.37 h118.11
  text "Layer:" at 3331.29,-695.37 h118.11
  text "Ref: '.Board_Reference'" at 1756.94,-892.22 h118.11
  text "Variant: '.VariantName'" at 3331.3,-892.22 h118.11
  text "R" at -19.69,-989.96 h60
  text "Rev: '.Board_PCB_Revision'" at 1759.18,-1089.07 h118.11
  text "Date: '.Board_Document_Date'" at 3331.3,-1089.07 h118.11

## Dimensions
3937.01,413.39 to 3937.01,905.51 on M2-Board Dimensions
2834.65,413.39 to 3937.01,413.39 on M2-Board Dimensions
0,905.51 to 0,0 on M2-Board Dimensions
0,0 to 2834.65,0 on M2-Board Dimensions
